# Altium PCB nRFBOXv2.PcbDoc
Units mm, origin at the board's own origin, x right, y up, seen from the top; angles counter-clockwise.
Board outline 47.75 x 87.5 mm, 2 copper layers (Top Layer, Bottom Layer); 68 components, 63 nets, 332 pads, 74 vias.
Unrouted connection lines stored in the file: 1.
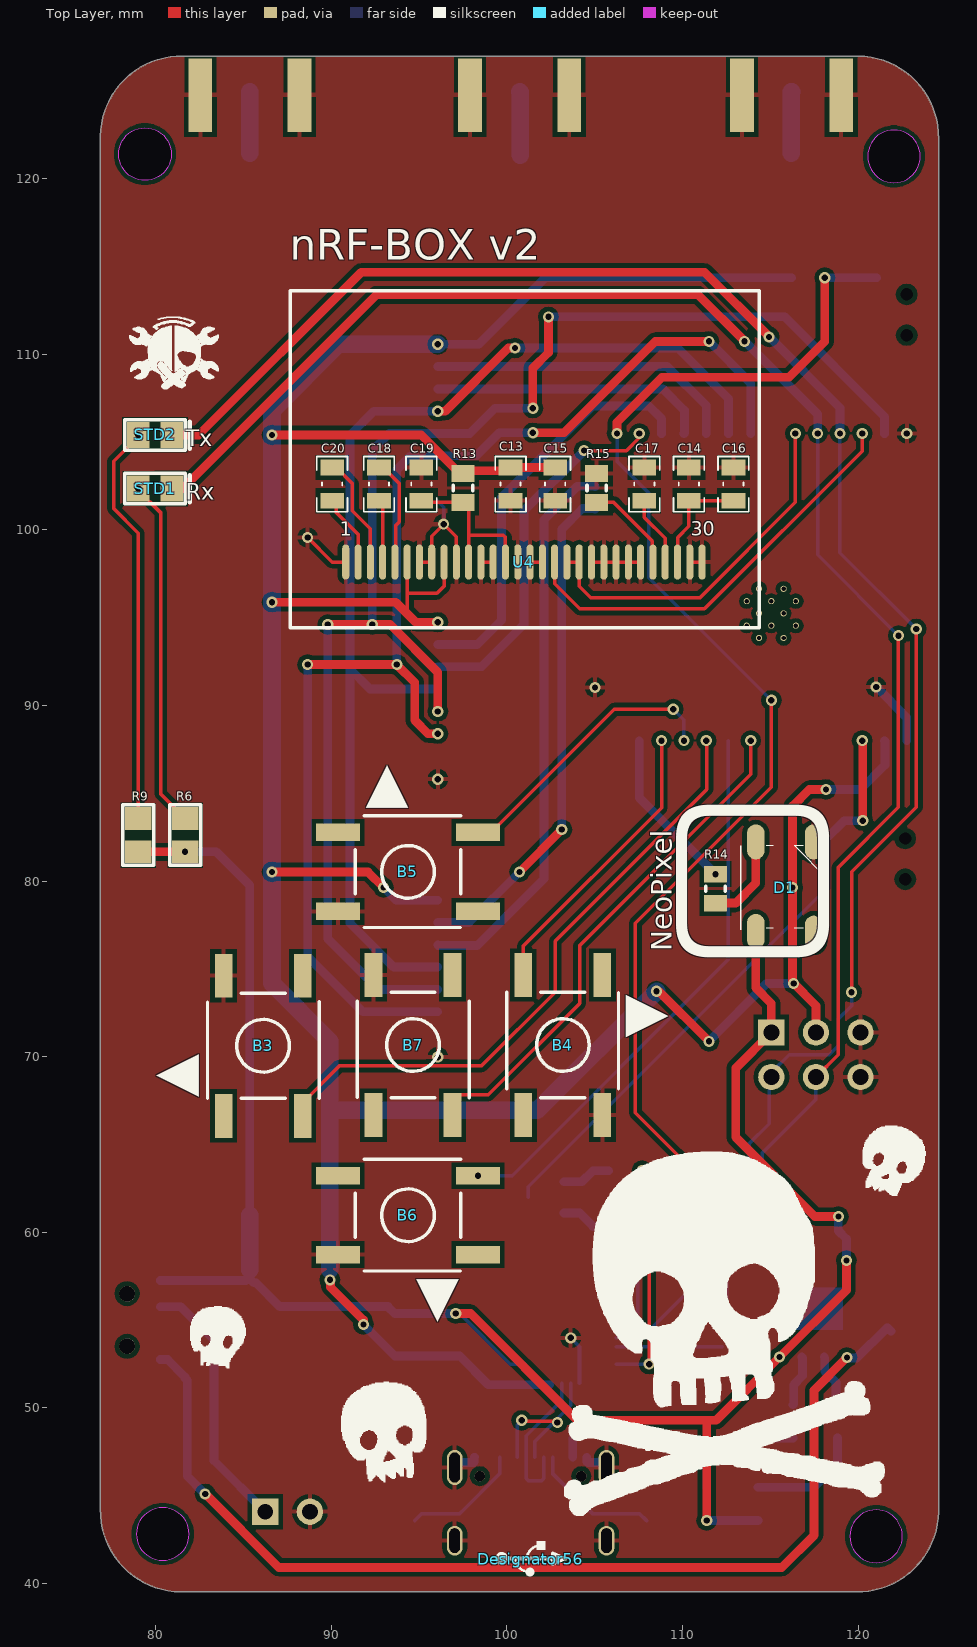
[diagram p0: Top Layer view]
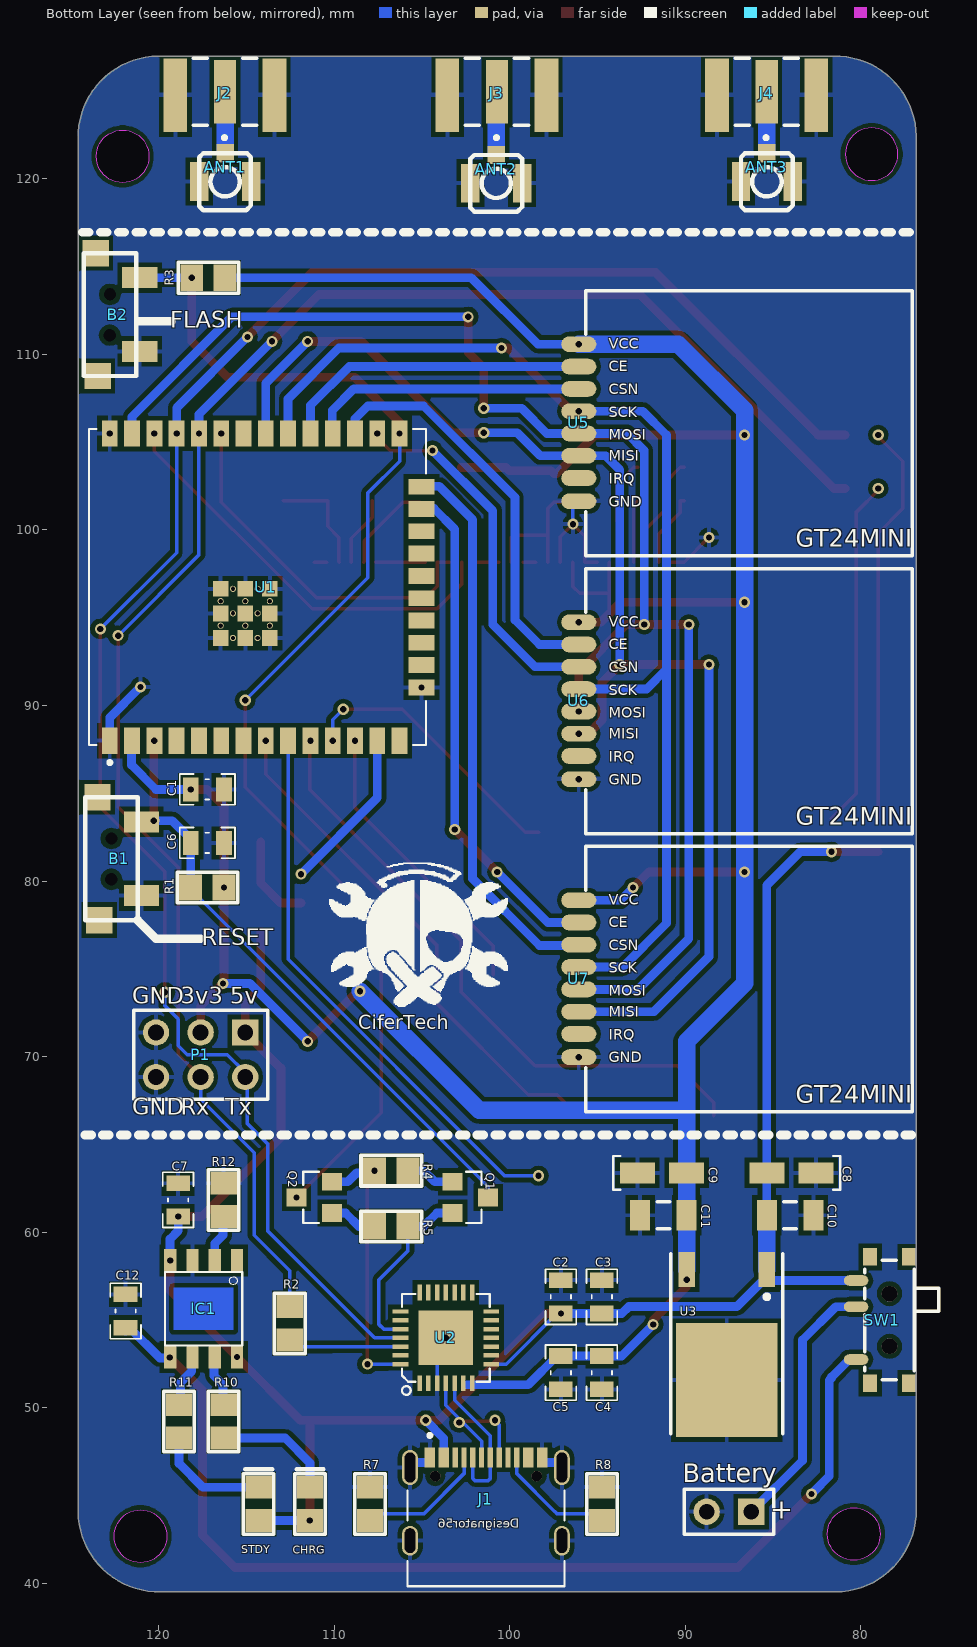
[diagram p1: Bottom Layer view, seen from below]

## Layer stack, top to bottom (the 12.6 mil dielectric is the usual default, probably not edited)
Top Solder: solder mask 0.0102, Solder Resist, Dk 3.5
Top Layer: signal copper 0.0356
Dielectric 1: dielectric 0.32, FR-4, Dk 4.8
Bottom Layer: signal copper 0.0356
Bottom Solder: solder mask 0.0102, Solder Resist, Dk 3.5

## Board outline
76.835,44.196 ccw(c81.47,44.133) 81.407,39.497 119.888,39.497 ccw(c119.951,44.132) 124.587,44.069 124.587,122.301 ccw(c119.952,122.364) 120.015,127 81.534,127 ccw(c81.471,122.365) 76.835,122.428
cut-out: 78.891,42.799 ccw(c80.391,42.799) 80.391,41.299 ccw(c80.391,42.799) 81.891,42.799 ccw(c80.391,42.799) 80.391,44.299 ccw(c80.391,42.799)
cut-out: 119.531,42.672 ccw(c121.031,42.672) 121.031,41.172 ccw(c121.031,42.672) 122.531,42.672 ccw(c121.031,42.672) 121.031,44.172 ccw(c121.031,42.672)
cut-out: 79.375,119.912 cw(c79.375,121.412) 77.875,121.412 cw(c79.375,121.412) 79.375,122.912 cw(c79.375,121.412) 80.875,121.412 cw(c79.375,121.412)
cut-out: 120.547,121.285 ccw(c122.047,121.285) 122.047,119.785 ccw(c122.047,121.285) 123.547,121.285 ccw(c122.047,121.285) 122.047,122.785 ccw(c122.047,121.285)

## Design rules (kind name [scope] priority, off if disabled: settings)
Clearance [All] p1: gap=0.254 ignorepadtopadclearanceinfootprint=FALSE except(0: Arc-Hole Track-Hole SMDPad-Hole THPad-Hole Via-Hole Fill-Hole Poly-Hole Region-Hole Text-Hole)
PolygonConnect [All] p1: connectstyle=Relief reliefconductorwidth=0.254 reliefentries=4 polygonreliefangle="90 Angle" airgapwidth=0.254
RoutingVias [All] p1: holewidth=0.711 width=1.27 viastyle="Through Hole" minholewidth=0.711 minwidth=1.27 maxholewidth=0.711 maxwidth=1.27
SolderMaskExpansion [All] p1: expansion=0.102
Width [All] p1: maxlimit=1 minlimit=0.2 preferedwidth=0.5 minimp=50.000000 maximp=50.000000 favimp=50.000000
30 further rules are at their usual default settings.

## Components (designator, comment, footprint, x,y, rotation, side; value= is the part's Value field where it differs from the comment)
ANT1 "ANT U.FL" "U.FL SMD" 116.205,120.65 r0 bottom
ANT2 "ANT U.FL" "U.FL SMD" 100.76,120.561 r0 bottom
ANT3 "ANT U.FL" "U.FL SMD" 85.344,120.65 r0 bottom
B1 "BUTTON" "PUSH BUTTON SMD" 122.67,81.178 r0 bottom
B2 "BUTTON" "PUSH BUTTON SMD" 122.759,112.177 r0 bottom
B3 "Button" "PUSH BUTTON 4 PIN SMD 5" 86.106,70.612 r90 top
B4 "Button" "PUSH BUTTON 4 PIN SMD 5" 103.187,70.657 r270 top
B5 "Button" "PUSH BUTTON 4 PIN SMD 5" 94.361,80.522 r180 top
B6 "Button" "PUSH BUTTON 4 PIN SMD 5" 94.361,60.96 r180 top
B7 "Button" "PUSH BUTTON 4 PIN SMD 5" 94.647,70.657 r90 top
Battery "Battery" Bat 69.342,53.721 r0 bottom (schematic designator BT1)
C1 "100nf" CAP0805 117.221,85.217 r0 bottom
C2 "10uf" CAP0805 97.079,56.311 r270 bottom
C3 "100nf" CAP0805 94.742,56.311 r270 bottom
C4 "10uf" CAP0805 94.742,51.993 r90 bottom
C5 "100nf" CAP0805 97.079,51.993 r90 bottom
C6 "100nf" CAP0805 117.221,82.169 r0 bottom
C7 "100nf" CAP0805 118.882,61.833 r270 bottom
C8 "Capacitor Tantalum SMD" "Tan 1206 (3216X18L) Size A" 77.211,68.835 r0 bottom value=2.2uf
C9 "Capacitor Tantalum SMD" "Tan 1206 (3216X18L) Size A" 98.049,57.913 r180 bottom value=2.2uf
C10 "10uf" "CAP 1206 (3216X15L)" 84.02,60.96 r0 bottom
C11 "10uf" "CAP 1206 (3216X15L)" 91.24,60.96 r180 bottom
C12 "100nf" CAP0805 121.88,55.504 r270 bottom
C13 "10uf" CAP0805 100.203,102.616 r270 top
C14 "10uf" CAP0805 110.363,102.616 r270 top
C15 "100nf" CAP0805 102.743,102.616 r270 top
C16 "100nf" CAP0805 112.903,102.616 r270 top
C17 "2.2uf" CAP0805 107.823,102.616 r90 top
C18 "1uf" CAP0805 92.71,102.616 r90 top
C19 "2.2uf" CAP0805 95.123,102.616 r90 top
C20 "1uf" CAP0805 90.043,102.616 r90 top
CHRG "LED" L0805 111.379,45.466 r90 bottom (schematic designator STD4)
D1 "LED RGB WS2812" "LED 5050 WS2812B" 115.824,79.629 r90 top
Designator56 "Comment" "LOGO USB1" 101.346,41.402 r0 top
IC1 "TP4056" SOP-8 117.435,55.631 r270 bottom
J1 "TYPE-C-31-M-12" HRO_TYPE-C-31-M-12 101.346,42.418 r180 bottom
J2 "SMA" SAMTEC_SMA-J-P-H-ST-EM1 116.216,124.968 r0 bottom
J3 "SMA" SAMTEC_SMA-J-P-H-ST-EM1 100.722,124.968 r0 bottom
J4 "SMA" SAMTEC_SMA-J-P-H-ST-EM1 85.355,124.968 r0 bottom
P1 "Header 3X2" HDR2X3 115.062,71.374 r0 bottom
Q1 "S8050" SOT-23 102.235,61.976 r270 bottom
Q2 "S8050" SOT-23 111.125,61.976 r90 bottom
R1 "4.7k" "RES 0805" 118.171,79.629 r270 bottom
R2 "470" "RES 0805" 112.522,55.753 r0 bottom
R3 "4.7k" "RES 0805" 118.107,114.372 r270 bottom
R4 "12k" "RES 0805" 107.691,63.5 r270 bottom
R5 "12k" "RES 0805" 105.791,60.325 r90 bottom
R6 "1k" "RES 0805" 81.666,81.661 r0 top
R7 "5.1k" "RES 0805" 107.95,43.566 r180 bottom
R8 "5.1k" "RES 0805" 94.742,43.566 r180 bottom
R9 "1k" "RES 0805" 78.999,81.666 r0 top
R10 "1k" "RES 0805" 116.292,50.165 r0 bottom
R11 "1k" "RES 0805" 118.832,50.165 r0 bottom
R12 "1k" "RES 0805" 116.292,60.883 r180 bottom
R13 "10k" "RES 0805 (2012X06L)" 97.49,101.568 r90 top
R14 "1k" "RES 0805 (2012X06L)" 111.887,80.39 r270 top
R15 "390k" "RES 0805 (2012X06L)" 105.11,101.568 r90 top
STD1 "LED" L0805 80.899,102.362 r0 top
STD2 "LED" L0805 80.899,105.41 r0 top
STDY "LED" L0805 114.3,45.466 r90 bottom (schematic designator STD3)
SW1 "SlideSwitch" SWSLIDT_SPDT_MSS3 78.359,54.991 r270 bottom
U1 "ESP32-WROOM-32U" XCVR_ESP32-WROOM-32U 114.369,96.747 r90 bottom
U2 "CP2102" QFN28G_0.5-5X5MM 103.632,53.975 r90 bottom
U3 "LF33" D-PACK 85.345,57.862 r0 bottom
U4 "OLED_0.96IN_WHITE" OLED_0.96IN_WHITE_SSD1306 100.965,98.171 r0 top locked
U5 "NRF24L01" NRF24L01_GT24MINI_MS 86.36,106.137 r180 bottom locked
U6 "NRF24L01" NRF24L01_GT24MINI_MS 86.36,90.302 r180 bottom locked
U7 "NRF24L01" NRF24L01_GT24MINI_MS 86.36,74.467 r180 bottom locked

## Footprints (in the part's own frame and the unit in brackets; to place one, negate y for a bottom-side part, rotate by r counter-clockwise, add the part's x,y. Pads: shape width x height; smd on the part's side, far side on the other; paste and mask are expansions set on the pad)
Bat [mm]
  rect 1.5x1.5 hole 0.9: 1(16.891,9.652)
  round 1.5 hole 0.9: 2(19.431,9.652)
  silkscreen extent 15.62,8.38 20.7,10.92
CAP0805 [mm] "Chip Capacitor, 2-Leads, Body 2/00x1/25mm, IPC Medium Density DESIGNER:ABBAS BASEREH"
  rect 0.9x1.35 smd: 1(-0.95,0) 2(0.95,0)
  silkscreen extent -1.58,-0.87 1.58,0.87, body extent -1.02,-0.65 1.02,0.65, height 0.5
"CAP 1206 (3216X15L)" [mm] "Chip Capacitor, 2-Leads, Body 3.2x1.6mm, IPC High Density"
  rect 1.15x1.75 smd: 1(-1.325,0) 2(1.325,0)
  silkscreen extent -0.35,-0.77 0.35,0.77, body extent -1.6,-0.8 1.6,0.8, height 1
D-PACK [mm] "D-PACK"
  rect 0.95x2 smd: 1(0,0) 3(4.57,0)
  rect 5.8x6.5 smd: 2(2.285,6.3)
  silkscreen extent -0.91,-0.9 5.49,9.35, body extent -1.03,-0.45 5.55,9.25, height 2.3
HDR2X3 [mm] "Connector; Header; 3x2 Position"
  rect 1.5x1.5 hole 0.9: 1(0,0)
  round 1.5 hole 0.9: 2(0,2.54) 3(2.54,0) 4(2.54,2.54) 5(5.08,0) 6(5.08,2.54)
  silkscreen extent -1.27,-1.27 6.35,3.81, body extent -1.27,-1.26 6.35,3.82, height 8.38
HRO_TYPE-C-31-M-12 [mm]
  rect 0.6x1.14 smd mask+0.05: A1_B12(-3.2,4.75) A4_B9(-2.4,4.75) B1_A12(3.2,4.75) B4_A9(2.4,4.75)
  rect 0.3x1.14 smd mask+0.05: A5(-1.25,4.75) A6(-0.25,4.75) A7(0.25,4.75) A8(1.25,4.75) B5(1.75,4.75) B6(0.75,4.75) B7(-0.75,4.75) B8(-1.75,4.75)
  oval 0.9x2 hole 0.6 slot 1.7 at 90 deg: S1(-4.325,4.17) S2(4.325,4.17)
  oval 0.9x1.7 hole 0.6 slot 1.4 at 90 deg: S3(-4.325,0) S4(4.325,0)
  round 0.6 hole 0.6 unplated: ""(-2.89,3.68) ""(2.89,3.68)
  silkscreen extent -4.47,-2.6 4.47,6.1, body extent -4.47,-2.6 4.47,5.3, height 3.31
L0805 [mm] "Body 2.0x1.3mm, IPC High Density"
  rect 1.3x1.5 smd: A(-1.9,0) K(0,0)
  silkscreen extent -2.68,-0.87 1.03,0.87, body extent -1.95,-0.63 0.05,0.62, height 0.68
"LED 5050 WS2812B" [mm]
  oval 2x1 smd: 1(-2.5,1.65) 2(-2.6,-1.65) 3(2.6,-1.65) 4(2.6,1.65)
  silkscreen extent -2.41,-2.49 2.4,2.51, body extent -2.74,-2.49 2.66,2.51, height 1.6
"LOGO USB1" [mm] "General USB Logo"
  silkscreen extent -1.82,-0.89 2.01,0.99
NRF24L01_GT24MINI_MS [mm] "2.4GHz Transceiver MODULE, SMD"
  oval 2x0.9 smd mask+0.1: 1(-9.7,4.44) 2(-9.7,3.17) 3(-9.7,1.9) 4(-9.7,0.63) 5(-9.7,-0.64) 6(-9.7,-1.91) 7(-9.7,-3.18) 8(-9.7,-4.5)
  silkscreen extent -9.3,-7.6 9.3,7.5, body extent -9.2,-7.5 9.2,7.4, height 2.25
OLED_0.96IN_WHITE_SSD1306 [mm] "OLED, 0.96IN, Monochrome white, SSD1306"
  oval 0.4x2 smd: 1(-10.15,0) 2(-9.45,0) 3(-8.75,0) 4(-8.05,0) 5(-7.35,0) 6(-6.65,0) 7(-5.95,0) 8(-5.25,0) 9(-4.55,0) 10(-3.85,0) 11(-3.15,0) 12(-2.45,0) 13(-1.75,0) 14(-1.05,0) 15(-0.35,0) 16(0.35,0) 17(1.05,0) 18(1.75,0) 19(2.45,0) 20(3.15,0) 21(3.85,0) 22(4.55,0) 23(5.25,0) 24(5.95,0) 25(6.65,0) 26(7.35,0) 27(8.05,0) 28(8.75,0) 29(9.45,0) 30(10.15,0)
  silkscreen extent -13.3,-3.75 13.4,15.45, body extent -13.35,-6.82 13.35,15.4, height 3.82
"PUSH BUTTON 4 PIN SMD 5" [mm]
  rect 2.5x1 smd: 1(-3.992,2.25) 2(-3.992,-2.25) 3(3.992,-2.25) 4(3.992,2.25)
  silkscreen extent -3,-3.2 3,3.17, body extent -4.5,-3 4.5,3, height 5
"PUSH BUTTON SMD" [mm]
  rect 1.5x1.5 smd: 1(0.712,3.405) 4(0.812,-3.595)
  rect 2x1.2 smd: 2(-1.688,2.005) 3(-1.688,-2.195)
  round 0 hole 0.7: ""(0.012,-1.245) ""(0.02,1.079)
  silkscreen extent -1.49,-3.59 1.51,3.41
QFN28G_0.5-5X5MM [mm]
  rect 0.9x0.254 smd: 1(-2.59,1.5) 2(-2.59,1) 3(-2.59,0.5) 4(-2.59,0) 5(-2.59,-0.5) 6(-2.59,-1) 7(-2.59,-1.5) 15(2.59,-1.5) 16(2.59,-1) 17(2.59,-0.5) 18(2.59,0) 19(2.59,0.5) 20(2.59,1) 21(2.59,1.5)
  rect 0.254x0.9 smd: 8(-1.5,-2.59) 9(-1,-2.59) 10(-0.5,-2.59) 11(0,-2.59) 12(0.5,-2.59) 13(1,-2.59) 14(1.5,-2.59) 22(1.5,2.59) 23(1,2.59) 24(0.5,2.59) 25(0,2.59) 26(-0.5,2.59) 27(-1,2.59) 28(-1.5,2.59)
  rect 3.1x3.1 smd paste-3: 29(0,0)
  silkscreen extent -3.25,-2.5 2.5,2.5
"RES 0805" [mm] "RES 0805"
  rect 1.5x1.3 smd: 1(0,0) 2(0,1.9)
  silkscreen extent -0.87,-0.77 0.87,2.68, body extent -0.63,-0.07 0.64,1.97, height 0.6
"RES 0805 (2012X06L)" [mm] "Chip Resistor, 2-Leads, Body 2.0x1.3mm, IPC High Density _ (0.100 W)"
  rect 0.95x1.3 smd: 1(0,0) 2(1.65,0)
  silkscreen extent 0.67,-0.55 0.97,0.55, body extent -0.19,-0.63 1.84,0.64, height 0.6
SAMTEC_SMA-J-P-H-ST-EM1 [mm]
  rect 1.27x3.6 smd: 1(0,0)
  rect 1.35x4.2 smd: 2_1(-2.825,0.2) 3_1(2.825,0.2)
  rect 1.35x4.2 smd far side: 2_2(-2.825,0.2) 3_2(2.825,0.2)
  silkscreen extent -1.8,-1.9 1.8,2.72, body extent -3.17,-11.42 3.18,1.91, height 3.55
SOP-8 [mm]
  rect 1.3x0.7 smd: 1(-2.75,1.905) 2(-2.75,0.635) 3(-2.75,-0.635) 4(-2.75,-1.905) 5(2.75,-1.905) 6(2.75,-0.635) 7(2.75,0.635) 8(2.75,1.905)
  Top Layer region: 1.2,-1.7 -1.2,-1.7 -1.2,1.7 1.2,1.7
  silkscreen extent -2.1,-2.2 2.1,2.2
SOT-23 [mil]
  rect 40x45 smd: 1(-35,-40) 2(35,-40) 3(0,40)
  silkscreen extent -58,-10 58,25, body extent -57,-51 57,51, height 55
SWSLIDT_SPDT_MSS3 [mm] "Switch, Slide, SPDT,"
  oval 0.6x1.4 smd: 1(2.25,-1.9) 2(-0.75,-1.9) 3(-2.25,-1.9)
  rect 1x0.8 smd: EP(-3.6,-1.1) EP(-3.6,1.1) EP(3.6,-1.1) EP(3.6,1.1)
  round 0.9 hole 0.9 unplated: ""(-1.5,0) ""(1.5,0)
  silkscreen extent -3.4,-1.4 3.4,2.8, body extent -3.85,-2.24 3.85,2.76, height 1.4
"Tan 1206 (3216X18L) Size A" [mil]
  rect 78.7x47.2 smd: 1(210,215) 2(320.22,215)
  silkscreen extent 156,177 171,253, body extent 193,179 336,250, height 71
"U.FL SMD" [mm] "U.FL Antenna-Design:Ali Hafizi"
  rect 1x1.05 smd: 1(0.002,-0.8)
  rect 1.05x2.2 smd: 2(-1.475,0.8) 2(1.475,0.8)
  silkscreen extent -1.47,-0.8 1.47,2.44, body extent -1.73,-0.76 1.67,2.34, height 1.25
XCVR_ESP32-WROOM-32U [mm]
  rect 1.5x0.9 smd: 1(-8.75,8.41) 2(-8.75,7.14) 3(-8.75,5.87) 4(-8.75,4.6) 5(-8.75,3.33) 6(-8.75,2.06) 7(-8.75,0.79) 8(-8.75,-0.48) 9(-8.75,-1.75) 10(-8.75,-3.02) 11(-8.75,-4.29) 12(-8.75,-5.56) 13(-8.75,-6.83) 14(-8.75,-8.1) 25(8.75,-8.1) 26(8.75,-6.83) 27(8.75,-5.56) 28(8.75,-4.29) 29(8.75,-3.02) 30(8.75,-1.75) 31(8.75,-0.48) 32(8.75,0.79) 33(8.75,2.06) 34(8.75,3.33) 35(8.75,4.6) 36(8.75,5.87) 37(8.75,7.14) 38(8.75,8.41)
  rect 0.9x1.5 smd: 15(-5.715,-9.35) 16(-4.445,-9.35) 17(-3.175,-9.35) 18(-1.905,-9.35) 19(-0.635,-9.35) 20(0.635,-9.35) 21(1.905,-9.35) 22(3.175,-9.35) 23(4.445,-9.35) 24(5.715,-9.35)
  rect 0.9x0.9 smd: 39_1(-2.9,2.09) 39_2(-1.5,2.09) 39_3(-0.1,2.09) 39_4(-2.9,0.69) 39_5(-1.5,0.69) 39_6(-0.1,0.69) 39_7(-2.9,-0.71) 39_8(-1.5,-0.71) 39_9(-0.1,-0.71)
  round 0.35 hole 0.25 mask+0: 40_1(-2.2,2.09) 40_2(-0.8,2.09) 40_3(-2.9,1.39) 40_4(-1.5,1.39) 40_5(-0.1,1.39) 40_6(-2.2,0.69) 40_7(-0.8,0.69) 40_8(-2.9,-0.01) 40_9(-1.5,-0.01) 40_10(-0.1,-0.01) 40_11(-2.2,-0.71) 40_12(-0.8,-0.71)
  silkscreen extent -10.1,-9.6 9,9.6, body extent -9,-9.6 9,9.6, height 3.35

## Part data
ANT1 ANT2 ANT3: "Antenna"
B1 B2: library part "PUSH BUTTON RIGHT", "PUSH BUTTON"
B3 B4 B5 B6 B7: library part "PUSH BUTTON 4 PIN", "PUSH BUTTON"
C1 C2 C3 C4 C5 C6 C7 C10 C11 C12 C13 C14 C15 C16 C17 C18 C19 C20: library part "CAP SMD", "Capacitor"
D1: "LED"
IC1: "Complete single cell Li-Ion battery with a constant current / constant voltage linear charger", Package="Package Analog Devices"
J1: "USB Connectors 24 Receptacle 1 8.94*7.3mm RoHS", Package=Package
J2 J3 J4: library part SMA-J-P-H-ST-EM1, "SMA Connector Jack, Female Socket 50Ohm Board Edge, End Launch Solder", Package=None
P1: "Header, 3-Pin, Dual row"
Q1 Q2: library part SMD-TRANSISTORS-NPN-25V-500MW(SOT-23), "Bipolar (BJT) Transistor NPN 25 V 500 mA 150MHz 300 mW Surface Mount SOT-23", Package=None
R1 R2 R3 R4 R5 R6 R7 R8 R9 R10 R11 R12 R13 R14 R15: library part RES, "RESISTOR"
SW1: library part SWSLIDT_SPDT_MSS3, "SWITCH, SLIDE, SPDT, SMD"
U1: "Bluetooth, WiFi 802.11b/g/n, Bluetooth v4.2 +EDR, Class 1, 2 and 3 Transceiver Module 2.4GHz ~ 2.5GHz Antenna Not Included, U.FL Surface Mount", Package="NON STANDARD-39 Espressif"
U2: library part INTERFACE-CP2102-GMR(QFN28), "USB Bridge, USB to UART USB 2.0 UART Interface 28-QFN _5x5_", Package="VFQFN-28 Vishay Siliconix"
U3: "3.3V VOLTAGE REGULATOR"
U4: library part OLED_0.96IN_WHITE_SSD1306, "OLED, 0.96\", Monochrome white, SSD1306"
U5 U6 U7: library part NRF24L01_GT24MINI_MS, "2.4GHz Transceiver MODULE, SMD"

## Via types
v1: diameter 0.635, hole 0.356, Top Layer to Bottom Layer, 74 vias

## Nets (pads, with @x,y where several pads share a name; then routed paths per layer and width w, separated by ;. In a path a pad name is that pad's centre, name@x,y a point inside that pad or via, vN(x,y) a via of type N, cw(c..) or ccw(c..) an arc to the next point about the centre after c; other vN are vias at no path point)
3V3: C1.2 C4.2 C5.2 C9.2 C11.2 C13.1 C15.1 P1.3 R1.2 R3.2 R13.2 U1.2 U2.6 U2.7 U3.3 U4.6 U4.9 U5.1 U6.1 U7.1 | length 195.6
  Top Layer w0.2: 94.24,95.313 94.315,95.389 94.315,96.393 ; U4.6 94.315,96.393 ; U4.9 96.415,96.796 96.012,96.393 94.315,96.393
  Top Layer w0.5: v1(86.614,80.518) 92.075,80.518 v1(92.964,79.629) ; v1(86.614,95.885) 93.668,95.885 94.24,95.313 94.811,94.742 v1(96.06,94.742) ; v1(86.614,105.41) 95.122,105.41 97.315,103.218 R13.2 97.65,103.378 100.015,103.378 C13.1 C15.1 ; v1(89.915,57.278) 89.941,57.252 89.941,56.871 91.821,54.991 v1(91.821,54.737) ; v1(108.521,73.724) 108.648,73.724 v1(111.506,70.866) ; P1.3 117.602,72.898 116.271,74.229 v1(116.271,79.629) 116.271,84.267 117.221,85.217 v1(118.171,85.217)
  Bottom Layer w0.5: v1(89.915,57.278) U3.3 ; v1(91.821,54.737) 93.615,52.943 C4.2 C5.2 97.304,52.943 98.939,51.308 102.424,51.308 ; v1(92.964,79.629) 93.686,78.907 U7.1 ; v1(96.06,110.577) 98.385,110.577 102.18,114.372 R3.2 ; v1(111.506,70.866) 114.808,74.168 v1(116.332,74.168) ; v1(118.171,85.217) 120.142,85.217 121.539,86.614 121.539,87.967 U1.2
  Bottom Layer w1: U3.3 C11.2 C9.2 89.915,66.929 ; v1(96.06,110.577) 90.384,110.577 86.614,106.807 v1(86.614,105.41) v1(86.614,95.885) v1(86.614,80.518) 86.614,74.168 89.915,70.867 89.915,66.929 ; v1(108.521,73.724) 101.727,66.929 89.915,66.929
+5v: C2.2 C3.2 C7.2 C8.2 C10.2 CHRG.A D1.1 IC1.4 IC1.8 J1.A4_B9 P1.1 R6.1 R9.1 STDY.A SW1.3 U2.8 U3.1 | length 116.6
  Top Layer w0.5: R9.1 79.001,81.664 v1(81.663,81.664) R6.1 ; v1(97.079,55.361) 97.928,55.361 104.013,49.276 v1(104.775,49.276) 111.252,49.276 ; v1(111.379,43.566) 111.379,49.149 111.252,49.276 ; D1.1 114.173,77.128 114.173,73.914 115.062,73.025 P1.1 113.03,69.342 113.03,65.405 117.552,60.883 v1(118.882,60.883) ; v1(119.34,58.381) 119.34,56.691 v1(115.53,52.881) 111.925,49.276 111.252,49.276
  Bottom Layer w0.2: v1(97.079,55.361) 97.304,55.361 100.19,52.475 U2.8
  Bottom Layer w0.5: SW1.3 85.12,57.241 U3.1@85.345,57.466 ; v1(81.663,81.664) 83.436,81.664 85.345,79.755 C10.2 ; U3.1 U3.1@85.345,57.466 ; v1(97.079,55.361) C3.2 93.61,55.361 93.218,55.753 87.058,55.753 85.699,57.112 85.57,57.112 85.345,57.337 U3.1@85.345,57.466 ; J1.A4_B9 103.746,48.242 104.775,49.271 v1(104.775,49.276) ; v1(111.379,43.566) STDY.A ; v1(118.882,60.883) 118.872,60.873 118.872,60.071 119.34,59.603 v1(119.34,58.381)
  Bottom Layer w1: U3.1 C10.2
ACTIVE: U2.11
BAT: C12.2 IC1.5 SW1.1 | length 60.2
  Top Layer w0.5: v1(82.804,45.085) 86.995,40.894 115.658,40.894 117.498,42.734 117.498,50.99 v1(119.365,52.857)
  Bottom Layer w0.5: SW1.1 80.659,52.741 81.661,51.739 81.661,51.689 81.788,51.562 81.788,46.101 v1@82.677,45.212 ; IC1.5 119.389,52.832 119.933,52.832 121.655,54.554 121.68,54.554 C12.2@121.88,54.354
CC1: J1.A5 R7.1 | length 7.4
  Bottom Layer w0.2: J1.A5 102.596,46.244 104.898,43.942 107.574,43.942 R7.1
CC2: J1.B5 R8.1 | length 6.9
  Bottom Layer w0.2: R8.1 95.118,43.942 97.282,43.942 97.409,44.069 97.421,44.069 99.596,46.244 J1.B5
CTS: U2.23
D+: J1.A6 J1.B6 U2.4 | length 9.4
  Top Layer w0.2: v1(100.838,49.276) 100.901,49.212 102.806,49.212 v1(102.87,49.149)
  Bottom Layer w0.2: J1.B6 100.592,47.172 100.592,49.03 v1(100.838,49.276) ; J1.A6 101.596,48.092 103.632,50.128 U2.4
D-: J1.A7 J1.B7 U2.5 | length 8.6
  Bottom Layer w0.2: J1.B7 102.096,45.964 101.979,45.847 101.209,45.847 101.092,45.964 101.092,46.443 101.096,46.447 J1.A7 101.096,48.391 103.132,50.427 U2.5
DCD: U2.1
DSR: U2.27
DTR: Q2.2 R4.1 U2.28 | length 15.8
  Top Layer w0.2: v1(107.696,63.5) 108.101,63.095 v1(108.101,52.475)
  Bottom Layer w0.2: U2.28 v1(108.101,52.475)
  Bottom Layer w0.5: R4.1 107.818,63.373 108.712,63.373 109.22,62.865 Q2.2
GND: ANT1.2 ANT2.2 ANT3.2 B1.2 B2.2 B3.4 B4.4 B5.4 B6.4 B7.4 Battery.2 C1.1 C2.1 C3.1 C4.1 C5.1 C6.1 C7.1 C8.1 C9.1 C10.1 C11.1 C12.1 C13.2 C14.1 C15.2 C16.1 C17.2 C19.2 D1.3 IC1.3 J1.A1_B12 J1.B1_A12 J1.S1 J1.S2 J1.S3 J1.S4 J2.2_1 J2.2_2 J2.3_1 J2.3_2 J3.2_1 J3.2_2 J3.3_1 J3.3_2 J4.2_1 J4.2_2 J4.3_1 J4.3_2 P1.5 P1.6 R7.2 R8.2 R12.2 R15.2 U1.1 U1.15 U1.38 U1.39_1 U1.39_2 U1.39_3 U1.39_4 U1.39_5 U1.39_6 U1.39_7 U1.39_8 U1.39_9 U2.3 U2.29 U3.2 U4.1 U4.7 U4.8 U4.10 U4.12 U4.13 U4.15 U4.16 U4.17 U4.21 U4.22 U4.23 U4.24 U4.25 U4.29 U4.30 U5.8 U6.8 U7.8 | length 25.1
  Top Layer w0.2: v1(88.646,99.568) 90.043,98.171 U4.1 ; U4.7 U4.8 95.715,99.652 v1(96.393,100.33) 97.115,99.608 U4.10 ; U4.12 U4.13 ; U4.15 U4.16 U4.17 ; U4.21 U4.22 U4.23 U4.24 U4.25 ; U4.29 U4.30
  Bottom Layer w0.2: U5.8 96.393,101.304 v1(96.393,100.33) ; v1(103.632,53.975) 104.132,53.475 U2.3
  Bottom Layer w0.5: J1.S2 97.021,46.693 97.206,46.878 98.096,46.878 98.142,46.924 98.142,47.164 J1.B1_A12 ; J1.A1_B12 104.55,47.168 104.55,46.924 104.596,46.878 105.486,46.878 105.671,46.693 J1.S1 ; v1(121.031,91.059) 122.779,89.311 U1.1
  other v1: 96.06,69.967 96.06,85.802 105.019,91.032 122.779,105.497
GPIO0: B2.3 Q2.3 R3.1 U1.25 | length 73.4
  Top Layer w0.2: v1(112.141,61.976) 107.315,66.802 107.315,77.597 115.062,85.344 v1(115.062,90.297)
  Top Layer w0.5: v1(106.269,105.497) 106.269,106.142 108.832,108.705 116.071,108.705 118.107,110.741 v1(118.107,114.372)
  Bottom Layer w0.2: v1(106.269,105.497) 106.269,103.916 108.077,102.108 108.077,97.282 v1(115.062,90.297)
  Bottom Layer w0.5: v1(118.107,114.372) B2.3
IO2: U1.24 U7.3 | length 31.8
  Bottom Layer w0.5: U7.3 96.1,76.327 98.298,76.327 102.108,80.137 102.108,100.584 104.013,102.489 104.992,102.489 U1.24
IO4: U1.26 U6.3 | length 20.9
  Top Layer w0.2: v1(104.394,104.521) 106.807,104.521 107.539,105.253 v1(107.539,105.497)
  Bottom Layer w0.5: U6.3 98.552,92.202 100.965,94.615 100.965,101.092 v1(104.394,104.521)
IO5: U1.29 U5.2 | length 17.8
  Bottom Layer w0.5: U5.2 109.133,109.307 111.349,107.091 U1.29
IO12: U1.14
IO13: U1.16
IO14: R14.1 U1.13 | length 9.4
  Bottom Layer w0.5: U1.13 107.539,84.738 v1(111.887,80.39)
IO15: U1.23 U7.2 | length 28.8
  Top Layer w0.5: v1(100.711,80.518) v1(103.124,82.931)
  Bottom Layer w0.5: U7.2 97.83,77.637 v1(100.711,80.518) ; v1(103.124,82.931) 103.124,100.037 104.306,101.219 104.992,101.219 U1.23
IO16: U1.27 U6.2 | length 23.6
  Bottom Layer w0.5: U6.2 98.298,93.472 99.695,94.869 99.695,101.854 104.902,107.061 108.077,107.061 108.809,106.329 U1.27
IO17: U1.28 U5.3 | length 15.9
  Bottom Layer w0.5: U5.3 108.879,108.037 110.109,106.807 110.109,105.527 U1.28
IO18: U1.30 U5.4 U6.4 U7.4 | length 66.1
  Top Layer w0.5: v1(96.06,106.767) 96.48,106.767 100.076,110.363 v1(100.457,110.363)
  Bottom Layer w0.5: U7.4 93.559,75.097 91.059,77.597 91.059,92.075 ; U6.4 92.202,90.932 91.059,92.075 ; v1(96.06,106.767) 92.416,106.767 91.059,105.41 91.059,92.075 ; v1(100.457,110.363) 109.728,110.363 112.619,107.472 U1.30
IO19: U1.31 U5.6 U6.6 U7.6 | length 73.8
  Top Layer w0.5: v1(88.646,92.329) v1(93.726,92.329) 94.742,91.313 94.742,89.154 95.504,88.392 v1(96.06,88.392) ; v1(101.473,105.537) 103.251,105.537 108.458,110.744 v1(111.506,110.744)
  Bottom Layer w0.5: v1(88.646,92.329) 88.646,75.692 91.781,72.557 U7.6 ; v1(93.726,92.329) 93.726,103.433 94.52,104.227 U5.6 98.258,104.227 99.568,105.537 v1(101.473,105.537) ; v1(111.506,110.744) 113.889,108.361 U1.31
IO21: U1.33 U4.19 U4.20 | length 20.8
  Top Layer w0.2: U4.19 U4.20 104.115,96.799 104.775,96.139 110.998,96.139 116.429,101.57 v1(116.429,105.497)
IO22: U1.36 U4.18 | length 24.1
  Top Layer w0.2: U4.18 102.715,96.929 104.14,95.504 111.252,95.504 120.239,104.491 v1(120.239,105.497)
IO23: U1.37 U5.5 U6.5 U7.5 | length 83.1
  Top Layer w0.5: v1(89.789,94.615) v1(92.329,94.615) 93.345,94.615 96.06,91.9 v1(96.06,89.662) ; v1(101.473,106.934) 101.473,109.22 102.362,110.109 v1(102.362,112.141)
  Bottom Layer w0.5: v1(89.789,94.615) 89.789,76.708 92.67,73.827 U7.5 ; v1(92.329,94.615) 92.329,104.521 93.305,105.497 U5.5 97.877,105.497 99.314,106.934 v1(101.473,106.934) ; v1(102.362,112.141) 115.824,112.141 121.509,106.456 U1.37
IO25: B3.2 U1.10 | length 35.7
  Top Layer w0.2: B3.2 88.356,67.369 90.455,69.469 98.552,69.469 102.743,73.66 102.743,76.581 111.379,85.217 111.379,87.967 v1(111.349,87.997)
IO26: B5.2 U1.11 | length 16.1
  Top Layer w0.2: B5.2 99.103,82.772 106.121,89.789 v1(109.474,89.789)
  Bottom Layer w0.2: v1(109.474,89.789) 110.079,89.184 v1(110.079,87.997)
IO27: B4.2 U1.12 | length 16.6
  Top Layer w0.2: B4.2 100.937,76.299 108.809,84.171 v1(108.809,87.997)
IO32: B7.2 U1.8 | length 29.3
  Top Layer w0.2: B7.2 96.896,67.414 97.297,67.814 98.929,67.814 104.14,73.025 104.14,76.327 113.889,86.076 v1(113.889,87.997)
IO33: B6.2 U1.9 | length 31.8
  Bottom Layer w0.2: v1(98.353,63.21) 100.294,63.21 112.619,75.535 U1.9
IO34: U1.6
IO35: U1.7
NetANT1_1: ANT1.1 J2.1 | length 3.5
  Bottom Layer w1: ANT1.1 116.207,124.959 J2.1
NetANT2_1: ANT2.1 J3.1 | length 3.6
  Bottom Layer w1: J3.1 100.762,124.928 ANT2.1
NetANT3_1: ANT3.1 J4.1 | length 3.5
  Bottom Layer w1: ANT3.1 85.346,124.959 J4.1
NetBT1_1: Battery.1 SW1.2 | length 14.8
  Bottom Layer w0.5: SW1.2 81.419,55.741 83.312,53.848 83.312,46.99 Battery.1
NetC14_2: C14.2 C16.2 U4.28 | length 6.3
  Top Layer w0.2: U4.28 109.728,98.184 109.728,99.568 110.363,100.203 C14.2 C16.2
NetC17_1: C17.1 U4.27 | length 4
  Top Layer w0.2: C17.1 107.823,100.711 109.015,99.519 U4.27
NetC18_1: C18.1 U4.4 | length 3.6
  Top Layer w0.2: C18.1 92.915,101.461 U4.4
NetC18_2: C18.2 U4.5 | length 6.1
  Top Layer w0.2: C18.2 92.935,103.566 93.853,102.648 93.853,100.457 93.653,100.257 93.653,98.209 U4.5
NetC19_1: C19.1 R13.1 U4.11 U4.14 | length 9.5
  Top Layer w0.2: C19.1 95.221,101.568 R13.1 97.815,101.242 97.815,99.707 ; U4.11 97.815,99.707 ; U4.14 99.915,99.578 99.798,99.695 97.827,99.695 97.815,99.707
NetC20_1: C20.1 U4.2 | length 4.2
  Top Layer w0.2: C20.1 90.268,101.666 90.268,100.994 91.515,99.747 U4.2
NetC20_2: C20.2 U4.3 | length 6.4
  Top Layer w0.2: C20.2 90.268,103.566 91.186,102.648 91.186,101.092 92.215,100.063 U4.3
NetD1_4: D1.4 R14.2 | length 5.1
  Top Layer w0.5: R14.2 113.03,78.74 114.174,79.884 D1.4
NetIC1_2: IC1.2 R12.1 | length 2.7
  Bottom Layer w0.5: R12.1 116.332,60.843 116.332,59.817 116.8,59.349 IC1.2
NetIC1_6: IC1.6 R11.1 | length 3
  Bottom Layer w0.5: IC1.6 118.11,52.841 118.11,52.07 118.745,51.435 118.745,50.252 R11.1
NetIC1_7: IC1.7 R10.1 | length 3
  Bottom Layer w0.5: R10.1 116.332,50.205 116.332,51.308 116.84,51.816 116.84,52.841 IC1.7
NetQ1_1: Q1.1 R4.2 | length 2.8
  Bottom Layer w0.5: Q1.1 104.267,62.865 104.902,63.5 R4.2
NetQ2_1: Q2.1 R5.2 | length 2.7
  Bottom Layer w0.5: R5.2 108.585,60.325 109.347,61.087 Q2.1
NetR2_2: R2.2 U2.26 | length 6.1
  Bottom Layer w0.2: U2.26 110.109,53.475 110.101,53.467 R2.2@112.268,53.467
NetR6_2: R6.2 STD1.A | length 19.9
  Top Layer w0.2: v1(78.999,102.362) 78.999,102.262 80.264,100.997 80.264,84.963 R6.2
NetR9_2: R9.2 STD2.A | length 23
  Top Layer w0.2: R9.2 78.999,99.817 77.597,101.219 77.597,103.908 78.999,105.31 v1(78.999,105.41)
NetR10_2: CHRG.K R10.2 | length 6.9
  Bottom Layer w0.5: CHRG.K 111.379,46.863 112.781,48.265 R10.2
NetR11_2: R11.2 STDY.K | length 6.5
  Bottom Layer w0.5: STDY.K 117.475,45.466 118.832,46.823 R11.2
NetR15_1: R15.1 U4.26 | length 5.3
  Top Layer w0.2: R15.1 106.077,101.568 108.277,99.368 108.277,98.209 U4.26
RESET: B1.3 C6.2 Q1.3 R1.1 U1.3 | length 34.6
  Top Layer w0.5: v1(120.239,87.997) 120.269,87.967 v1(120.269,83.439)
  Bottom Layer w0.2: Q1.3 101.219,62.577 R1.1@118.171,79.529 ; R1.1@118.171,79.529 R1.1 R1.1@118.171,79.529
  Bottom Layer w0.5: R1.1 C6.2 118.171,82.394 119.216,83.439 v1(120.269,83.439)
RI: U2.2
RTS: Q1.2 R5.1 U2.24 | length 10.5
  Bottom Layer w0.2: R5.1 105.791,58.928 107.442,57.277 107.442,54.737 107.18,54.475 U2.24
  Bottom Layer w0.5: Q1.2 104.14,61.087 104.902,60.325 R5.1
RX_0: P1.4 R2.1 STD1.K U1.34 | length 101
  Top Layer w0.2: P1.4 118.872,70.104 118.872,80.772 122.301,84.201 v1(122.301,93.98)
  Top Layer w0.5: STD1.K 81.534,102.362 92.583,113.411 110.871,113.411 v1(113.538,110.744)
  Bottom Layer w0.2: R2.1 112.522,57.788 114.554,59.82 114.554,64.516 117.602,67.564 P1.4 ; v1(117.699,105.497) 117.699,98.582 v1(122.301,93.98)
  Bottom Layer w0.5: v1(113.538,110.744) 117.699,106.583 v1(117.699,105.497)
TX_0: P1.2 STD2.K U1.35 U2.25 | length 109.2
  Top Layer w0.2: v1(119.634,73.66) 119.634,80.518 123.317,84.201 v1(123.317,94.361)
  Top Layer w0.5: STD2.K 82.423,105.41 91.694,114.681 111.252,114.681 v1(114.935,110.998)
  Bottom Layer w0.2: U2.25 107.696,53.975 113.792,60.071 113.792,65.024 114.935,66.167 114.935,68.707 P1.2 115.062,69.088 116.078,70.104 118.364,70.104 118.872,70.612 118.872,72.136 119.634,72.898 v1(119.634,73.66) ; v1(118.969,105.497) 118.969,98.709 v1(123.317,94.361)
  Bottom Layer w0.5: v1(114.935,110.998) 118.969,106.964 v1(118.969,105.497)
pads on no net: B1. B1.1 B1.4 B2. B2.1 B2.4 B3.1 B3.3 B4.1 B4.3 B5.1 B5.3 B6.1 B6.3 B7.1 B7.3 D1.2 IC1.1 J1. J1.A8 J1.B4_A9 J1.B8 SW1. SW1.EP U1.4 U1.5 U1.17 U1.18 U1.19 U1.20 U1.21 U1.22 U1.32 U1.40_1 U1.40_2 U1.40_3 U1.40_4 U1.40_5 U1.40_6 U1.40_7 U1.40_8 U1.40_9 U1.40_10 U1.40_11 U1.40_12 U2.9 U2.10 U2.12 U2.13 U2.14 U2.15 U2.16 U2.17 U2.18 U2.19 U2.20 U2.21 U2.22 U5.7 U6.7 U7.7

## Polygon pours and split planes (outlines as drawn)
GND on Top Layer "Top Layer-No Net" (solid, pour order 2): 76.835,44.196 ccw(c81.47,44.133) 81.407,39.497 119.888,39.497 ccw(c119.951,44.132) 124.587,44.069 124.587,122.301 ccw(c119.952,122.364) 120.015,127 81.534,127 ccw(c81.471,122.365) 76.835,122.428
GND on Bottom Layer "Top Layer-No Net1" (solid, pour order 3): 76.835,44.196 ccw(c81.47,44.133) 81.407,39.497 119.888,39.497 ccw(c119.951,44.132) 124.587,44.069 124.587,122.301 ccw(c119.952,122.364) 120.015,127 81.534,127 ccw(c81.471,122.365) 76.835,122.428

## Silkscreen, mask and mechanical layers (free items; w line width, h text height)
Top Overlay:
  drawing of 3251 lines, arcs and shapes, not listed
  text "nRF-BOX v2" at 87.63,114.808 h3
  text "Tx" at 81.693,104.442 h1.6
  text "Rx" at 81.693,101.394 h1.6
  text "▲" at 91.948,83.782 h4
  text "NeoPixel" at 109.791,76.01 h2 r90
  text "▢" at 119.843,74.601 h15 r90
  text "▲" at 106.388,73.533 h4 r270
  text "▲" at 82.842,67.691 h4 r90
  text "▲" at 97.282,57.696 h4 r180
Bottom Overlay:
  drawing of 766 lines, arcs and shapes, not listed
  text "FLASH" at 119.323,111.22 h1.6
  text "RESET" at 117.545,76.041 h1.6
  text "5v" at 115.921,72.707 h1.6
  text "3v3" at 118.745,72.707 h1.6
  text "GND" at 121.509,72.707 h1.6
  text "CiferTech" at 108.61,71.552 h0.8
  text "Tx" at 116.205,66.358 h1.6
  text "Rx" at 118.745,66.358 h1.6
  text "GND" at 121.507,66.358 h1.6
Mechanical 1:
  circle w0.208: c121.031,42.672 r1.5
  circle w0.208: c122.047,121.285 r1.5
  circle w0.208: c80.391,42.799 r1.5
  circle w0.208: c79.375,121.412 r1.5
  lines w0.1: 76.835,44.196 ccw(c81.47,44.133) 81.407,39.497 119.888,39.497 ccw(c119.951,44.132) 124.587,44.069 124.587,122.301 ccw(c119.952,122.364) 120.015,127 81.534,127 ccw(c81.471,122.365) 76.835,122.428 76.835,44.196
